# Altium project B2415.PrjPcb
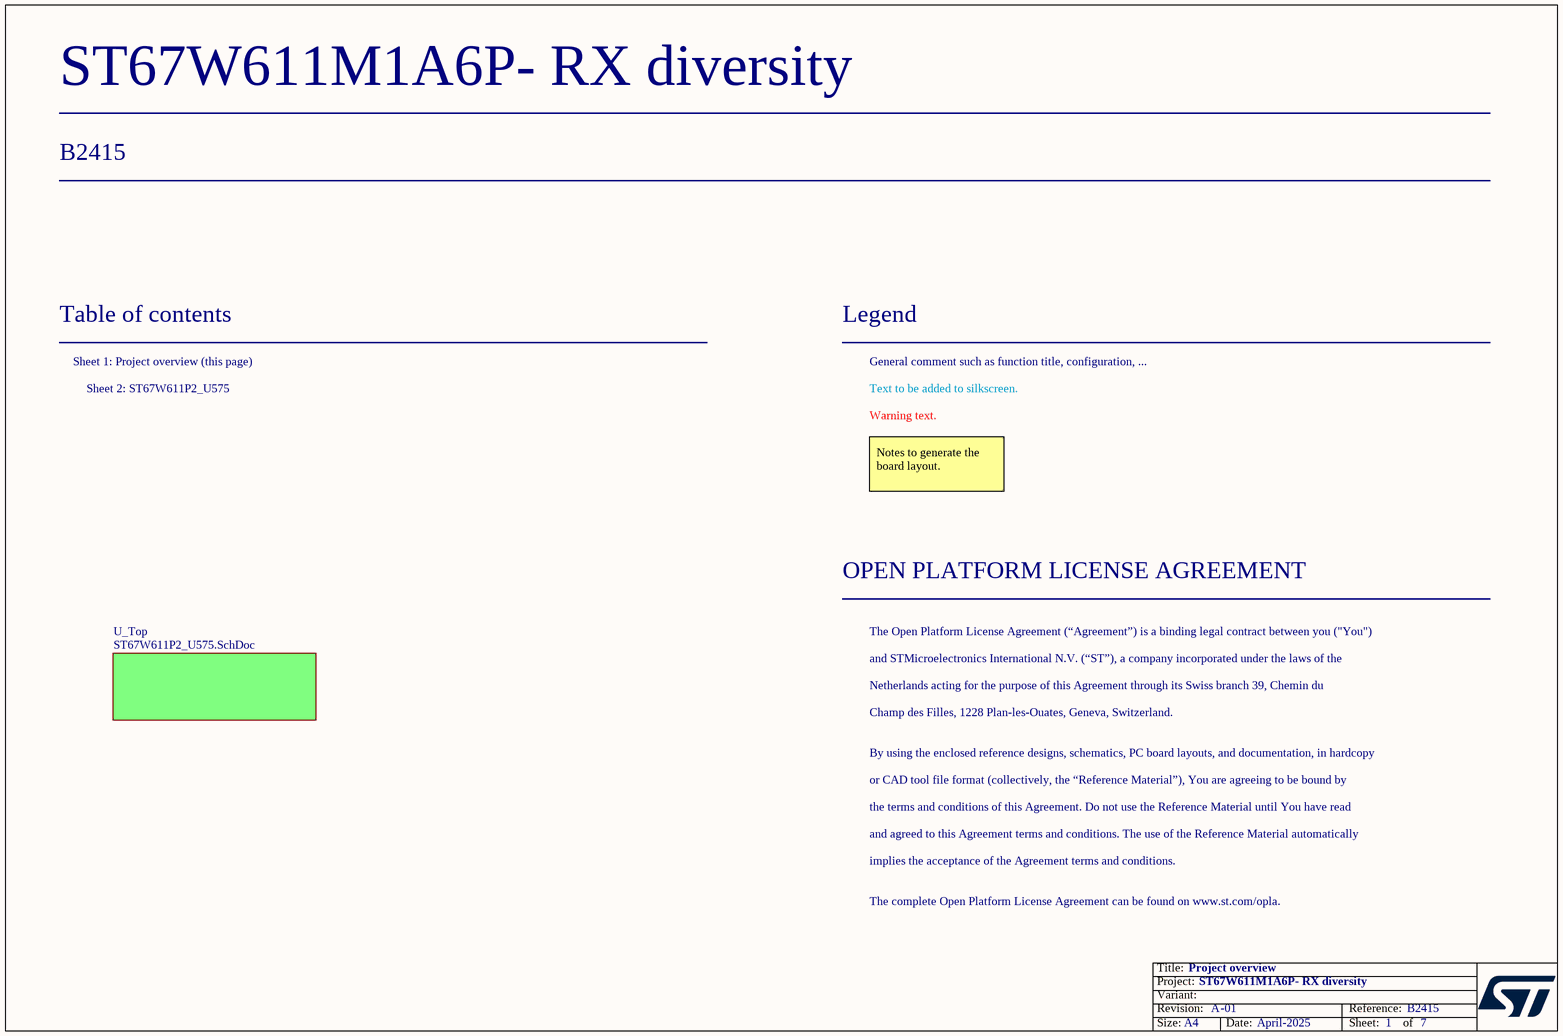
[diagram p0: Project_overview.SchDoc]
Board_Reference: B2415; Board_PCB_Revision: A; Board_Name: ST67W611M1A6P- RX diversity; Board_Document_Date: April-2025; Board_Assembly_Revision: 01
2 sheets, 94 parts. Net scope: global (net labels, ports and power ports of the same name join across sheets).
Board file: B2415.PcbDoc
Sheets:
  Project_overview.SchDoc
    U_Top = ST67W611P2_U575.SchDoc

## Sheet Project_overview.SchDoc: Project overview
size A4; Date: Not used; ApprovedBy: Not used; CheckedBy: Not used; Author: Not used; CompanyName: STMicroelectronics; DrawnBy: Not used; Engineer: Not used; Organization: Not used; Address1: Not used; Address2: Not used; Address3: Not used; Address4: Not used; DocumentNumber: Not used; Revision: Not used; SheetNumber: 1; SheetTotal: 7

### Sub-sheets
U_Top = ST67W611P2_U575.SchDoc: no entries

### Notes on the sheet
- Table of contents
- Sheet 1: Project overview (this page)
- Legend
- General comment such as function title, configuration, ...
- Sheet 2: ST67W611P2_U575
- Text to be added to silkscreen.
- Warning text.
- Notes to generate the board layout.
- OPEN PLATFORM LICENSE AGREEMENT
- The Open Platform License Agreement (“Agreement”) is a binding legal contract between you ("You")
- and STMicroelectronics International N.V. (“ST”), a company incorporated under the laws of the
- Netherlands acting for the purpose of this Agreement through its Swiss branch 39, Chemin du
- Champ des Filles, 1228 Plan-les-Ouates, Geneva, Switzerland.
- By using the enclosed reference designs, schematics, PC board layouts, and documentation, in hardcopy
- or CAD tool file format (collectively, the “Reference Material”), You are agreeing to be bound by
- the terms and conditions of this Agreement. Do not use the Reference Material until You have read
- and agreed to this Agreement terms and conditions. The use of the Reference Material automatically
- implies the acceptance of the Agreement terms and conditions.
- The complete Open Platform License Agreement can be found on www.st.com/opla.

## Sheet ST67W611P2_U575.SchDoc: STM32 microcontroller RF
size A3; Date: Not used; ApprovedBy: Not used; CheckedBy: Not used; Author: Not used; CompanyName: STMicroelectronics; DrawnBy: Not used; Engineer: Not used; Organization: Not used; Address1: Not used; Address2: Not used; Address3: Not used; Address4: Not used; DocumentNumber: Not used; Revision: Not used; SheetNumber: 5; SheetTotal: 7
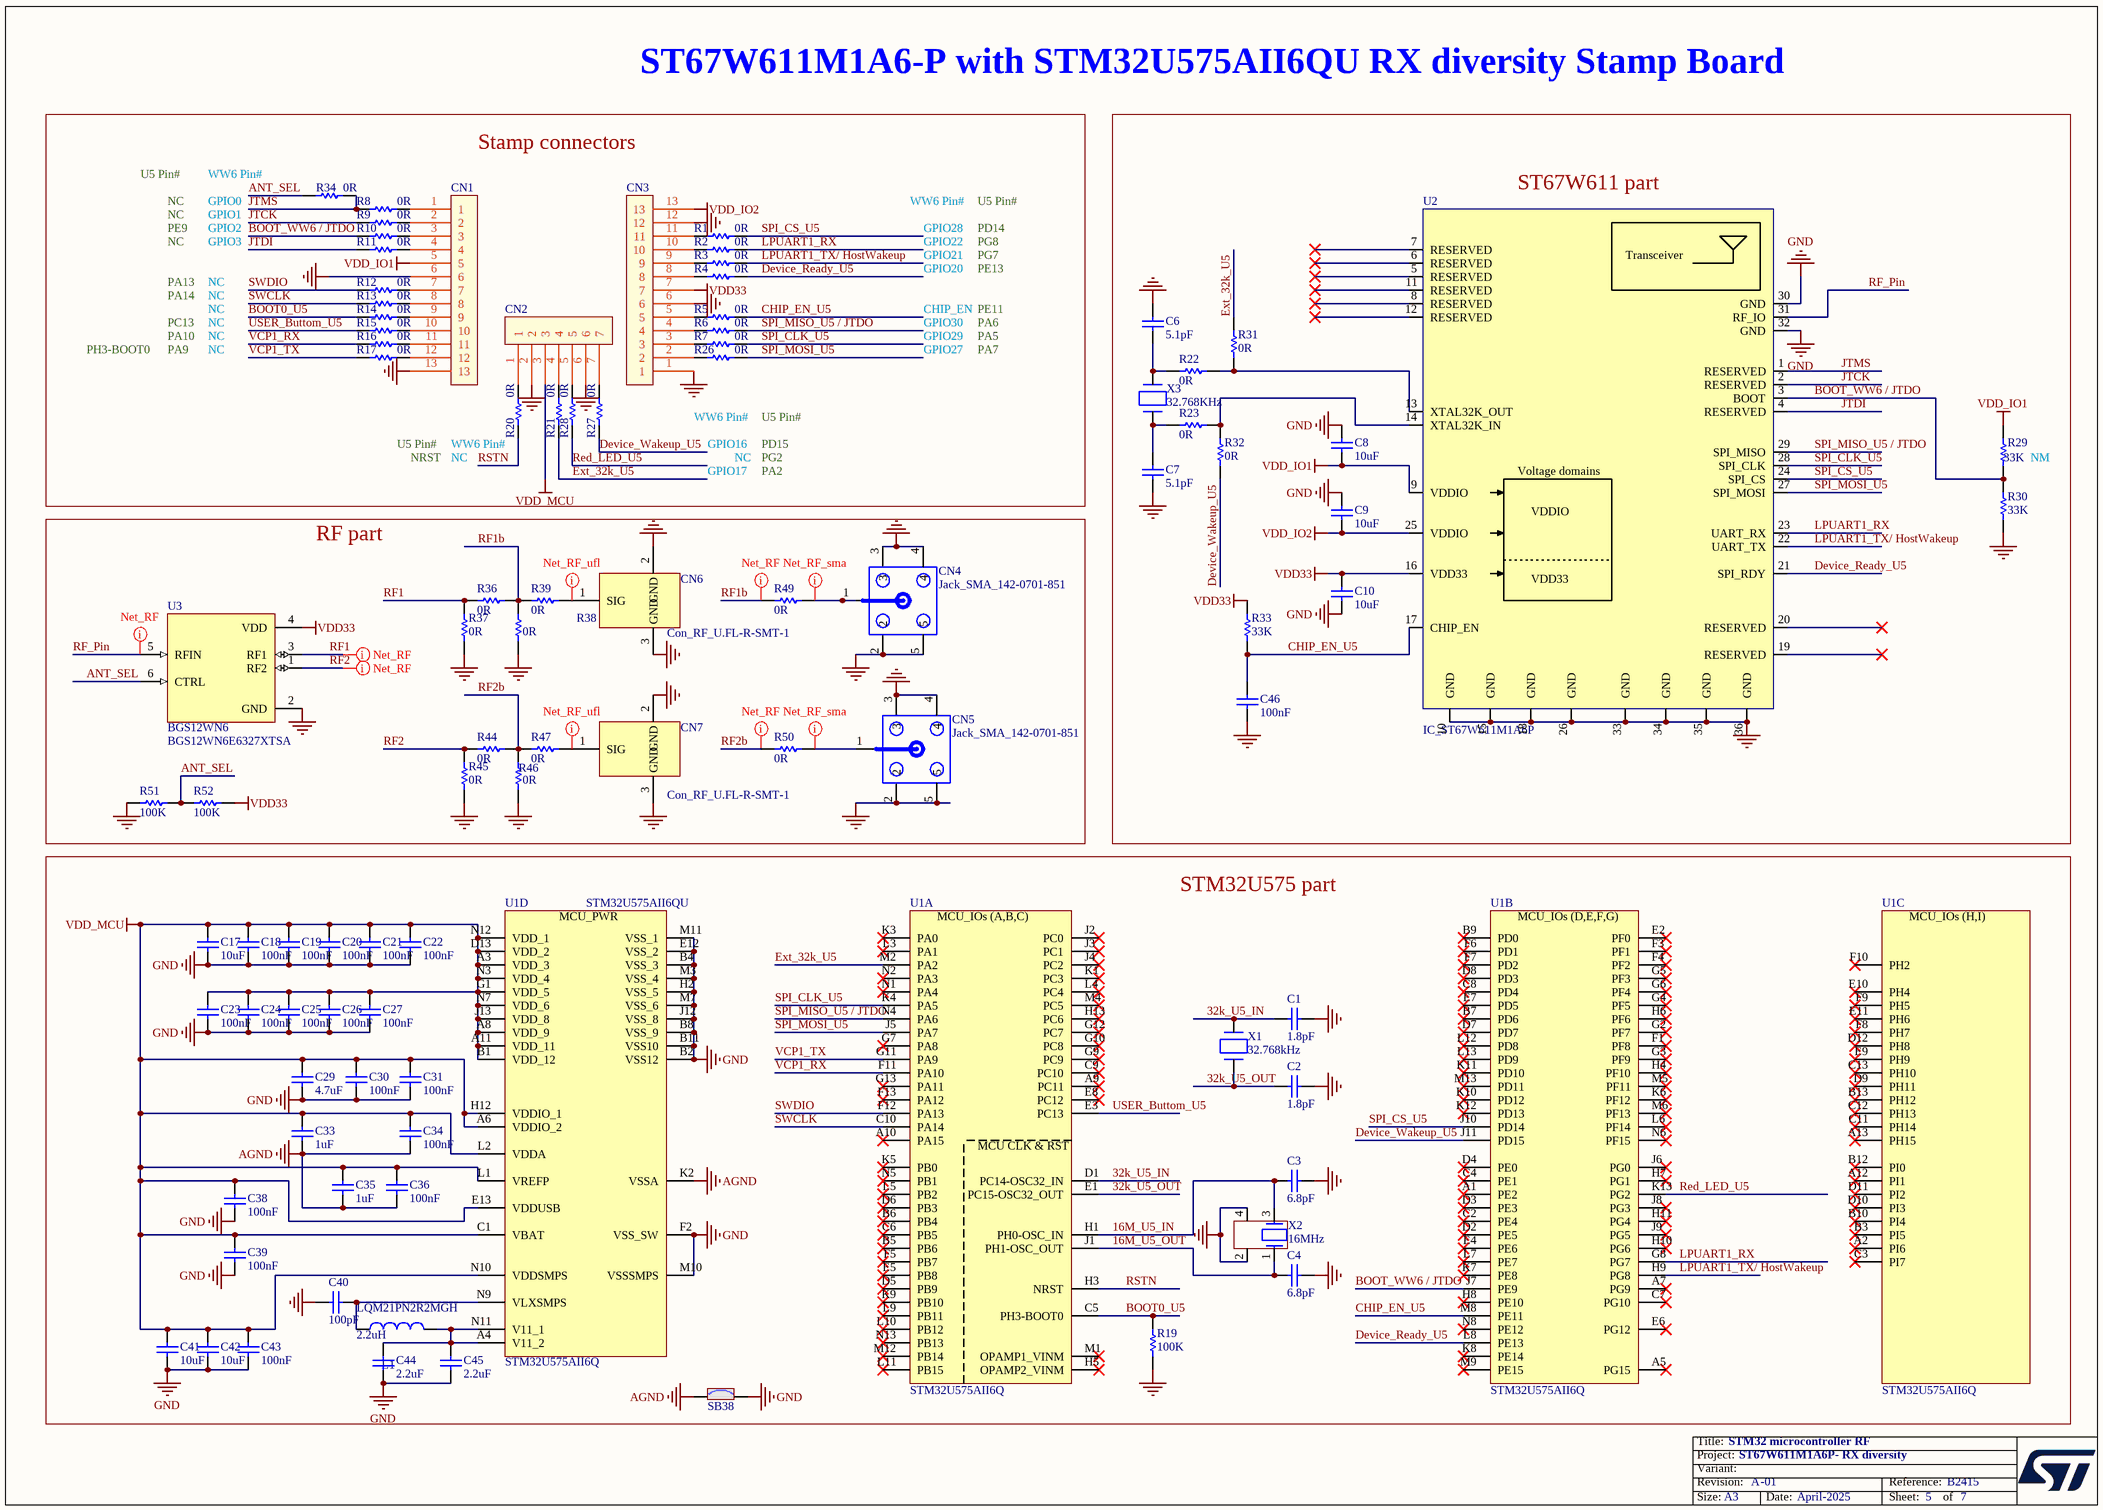
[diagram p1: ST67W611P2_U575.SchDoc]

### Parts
C1  value 1.8pF  [C0402]  (hidden comment: Capacitor)
C2  value 1.8pF  [C0402]  (hidden comment: Capacitor)
C3  value 6.8pF  [C0402]  (hidden comment: Capacitor)
C4  value 6.8pF  [C0402]  (hidden comment: Capacitor)
C6  value 5.1pF  [C0402]  (hidden comment: Capacitor)
C7  value 5.1pF  [C0402]  (hidden comment: Capacitor)
C8  value 10uF  [C0402]  (hidden comment: Capacitor)
C9  value 10uF  [C0402]  (hidden comment: Capacitor)
C10  value 10uF  [C0402]  (hidden comment: Capacitor)
C17  value 10uF  [C0402]  (hidden comment: Capacitor)
C18  value 100nF  [C0402]  (hidden comment: Capacitor)
C19  value 100nF  [C0402]  (hidden comment: Capacitor)
C20  value 100nF  [C0402]  (hidden comment: Capacitor)
C21  value 100nF  [C0402]  (hidden comment: Capacitor)
C22  value 100nF  [C0402]  (hidden comment: Capacitor)
C23  value 100nF  [C0402]  (hidden comment: Capacitor)
C24  value 100nF  [C0402]  (hidden comment: Capacitor)
C25  value 100nF  [C0402]  (hidden comment: Capacitor)
C26  value 100nF  [C0402]  (hidden comment: Capacitor)
C27  value 100nF  [C0402]  (hidden comment: Capacitor)
C29  value 4.7uF  [C0402]  (hidden comment: Capacitor)
C30  value 100nF  [C0402]  (hidden comment: Capacitor)
C31  value 100nF  [C0402]  (hidden comment: Capacitor)
C33  value 1uF  [C0402]  (hidden comment: Capacitor)
C34  value 100nF  [C0402]  (hidden comment: Capacitor)
C35  value 1uF  [C0402]  (hidden comment: Capacitor)
C36  value 100nF  [C0402]  (hidden comment: Capacitor)
C38  value 100nF  [C0402]  (hidden comment: Capacitor)
C39  value 100nF  [C0402]  (hidden comment: Capacitor)
C40  value 100pF  [C0402]  (hidden comment: Capacitor)
C41  value 10uF  [C0402]  (hidden comment: Capacitor)
C42  value 10uF  [C0402]  (hidden comment: Capacitor)
C43  value 100nF  [C0402]  (hidden comment: Capacitor)
C44  value 2.2uF  [C0402]  (hidden comment: Capacitor)
C45  value 2.2uF  [C0402]  (hidden comment: Capacitor)
C46  value 100nF  [C0402]  (hidden comment: Capacitor)
CN1  (no value)  [Stamps_holes_x13]
CN2  (no value)  [Stamps_holes_x7]
CN3  (no value)  [Stamps_holes_x13]
CN4  value Jack_SMA_142-0701-851  [CON_SMA-RF_CINCH_142-0701-851]  (hidden comment: SMA-J-P-H-ST-EM1)
CN5  value Jack_SMA_142-0701-851  [CON_SMA-RF_CINCH_142-0701-851]  (hidden comment: SMA-J-P-H-ST-EM1)
CN6  value Con_RF_U.FL-R-SMT-1  [CON_HRS_U.FL-R-SMT-1]  (hidden comment: U.FL-R-SMT-1)
CN7  value Con_RF_U.FL-R-SMT-1  [CON_HRS_U.FL-R-SMT-1]  (hidden comment: U.FL-R-SMT-1)
L1  value 2.2uH  Manufacturer_Part_Number: LQM21PN2R2MGH  [L0805_H0P9]  (hidden comment: Inductor)
R1  value 0R  [R0201_H0P23]  (hidden comment: Resistor)
R2  value 0R  [R0201_H0P23]  (hidden comment: Resistor)
R3  value 0R  [R0201_H0P23]  (hidden comment: Resistor)
R4  value 0R  [R0201_H0P23]  (hidden comment: Resistor)
R5  value 0R  [R0201_H0P23]  (hidden comment: Resistor)
R6  value 0R  [R0201_H0P23]  (hidden comment: Resistor)
R7  value 0R  [R0201_H0P23]  (hidden comment: Resistor)
R8  value 0R  [R0201_H0P23]  (hidden comment: Resistor)
R9  value 0R  [R0201_H0P23]  (hidden comment: Resistor)
R10  value 0R  [R0201_H0P23]  (hidden comment: Resistor)
R11  value 0R  [R0201_H0P23]  (hidden comment: Resistor)
R12  value 0R  [R0201_H0P23]  (hidden comment: Resistor)
R13  value 0R  [R0201_H0P23]  (hidden comment: Resistor)
R14  value 0R  [R0201_H0P23]  (hidden comment: Resistor)
R15  value 0R  [R0201_H0P23]  (hidden comment: Resistor)
R16  value 0R  [R0201_H0P23]  (hidden comment: Resistor)
R17  value 0R  [R0201_H0P23]  (hidden comment: Resistor)
R19  value 100K  [R0201_H0P23]  (hidden comment: Resistor)
R20  value 0R  [R0201_H0P23]  (hidden comment: Resistor)
R21  value 0R  [R0201_H0P23]  (hidden comment: Resistor)
R22  value 0R  [R0201_H0P23]  (hidden comment: Resistor)
R23  value 0R  [R0201_H0P23]  (hidden comment: Resistor)
R26  value 0R  [R0201_H0P23]  (hidden comment: Resistor)
R27  value 0R  [R0201_H0P23]  (hidden comment: Resistor)
R28  value 0R  [R0201_H0P23]  (hidden comment: Resistor)
R29  value 33K  [R0402]  (hidden comment: Resistor)
R30  value 33K  [R0402]  (hidden comment: Resistor)
R31  value 0R  [R0201_H0P23]  (hidden comment: Resistor)
R32  value 0R  [R0201_H0P23]  (hidden comment: Resistor)
R33  value 33K  [R0402]  (hidden comment: Resistor)
R34  value 0R  [R0201_H0P23]  (hidden comment: Resistor)
R36  value 0R  [R0201_H0P23]  (hidden comment: Resistor)
R37  value 0R  [R0201_H0P23]  (hidden comment: Resistor)
R38  value 0R  [R0201_H0P23]  (hidden comment: Resistor)
R39  value 0R  [R0201_H0P23]  (hidden comment: Resistor)
R44  value 0R  [R0201_H0P23]  (hidden comment: Resistor)
R45  value 0R  [R0201_H0P23]  (hidden comment: Resistor)
R46  value 0R  [R0201_H0P23]  (hidden comment: Resistor)
R47  value 0R  [R0201_H0P23]  (hidden comment: Resistor)
R49  value 0R  [R0201_H0P23]  (hidden comment: Resistor)
R50  value 0R  [R0201_H0P23]  (hidden comment: Resistor)
R51  value 100K  [R0201_H0P23]  (hidden comment: Resistor)
R52  value 100K  [R0201_H0P23]  (hidden comment: Resistor)
SB38  SB_ON  [SOLDER-BRIDGE_R0402-0R]  (value not drawn)
U1  value STM32U575AII6Q  [ICC_UFBGA169_7X7_P050]  (hidden comment: STM32U575AII6QU)  (parts A,B,C,D of 4)
U2  IC_ST67W611M1A6P  [ST67W611M1A6P/B6P]
U3  BGS12WN6  value BGS12WN6E6327XTSA  [ICC_TSNP-6-10_0P7X1P1_P040]
X1  value 32.768kHz  [CRY_NX1610SE_2P]  (hidden comment: XTAL_2_PINS)
X2  value 16MHz  [CRY_NX2016SA_4P]  (hidden comment: XTAL_4_PINS)
X3  value 32.768KHz  [CRY_NX2012SA_2P]  (hidden comment: XTAL_2_PINS)

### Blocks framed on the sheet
Stamp connectors: CN1-CN3 R1-R17 R20 R21 R26-R28 R34
ST67W611 part: C6-C10 C46 R22 R23 R29-R33 U2 X3
RF part: CN4-CN7 R36-R39 R44-R47 R49-R52 U3
STM32U575 part: C1-C4 C17-C27 C29-C31 C33-C36 C38-C45 L1 R19 SB38 U1 X1 X2

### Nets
AGND: C33.1 C34.1 C35.1 C36.1 SB38.1 U1.K2(VSSA)
GND: C1.1 C2.1 C3.1 C4.1 C6.2 C7.1 C8.2 C9.2 C10.1 C17.1 C18.1 C19.1 C20.1 C21.1 C22.1 C23.1 C24.1 C25.1 C26.1 C27.1 C29.1 C30.1 C31.1 C38.1 C39.1 C40.1 C41.1 C42.1 C43.1 C44.1 C45.1 C46.1 CN1.6 CN1.13 CN2.2 CN2.6 CN3.1 CN3.6 CN3.12 CN4.2 CN4.3 CN4.4 CN4.5 CN5.2 CN5.3 CN5.4 CN5.5 CN6.2(GND) CN6.3(GND) CN7.2(GND) CN7.3(GND) R19.2 R30.1 R37.1 R38.1 R45.1 R46.1 R51.1 SB38.2 U1.B2(VSS12) U1.B4(VSS_3) U1.B8(VSS_9) U1.B11(VSS10) U1.E12(VSS_2) U1.F2(VSS_SW) U1.H2(VSS_5) U1.J12(VSS_8) U1.M3(VSS_4) U1.M7(VSS_6) U1.M10(VSSSMPS) U1.M11(VSS_1) U2.10(GND) U2.15(GND) U2.18(GND) U2.26(GND) U2.30(GND) U2.32(GND) U2.33(GND) U2.34(GND) U2.35(GND) U2.36(GND) U3.2(GND) X2.2 X2.4
VDD33: C10.2 CN3.7 R33.2 R52.2 U2.16(VDD33) U3.4(VDD)
VDD_IO1: C8.1 CN1.5 R29.2 U2.9(VDDIO)
VDD_IO2: C9.1 CN3.13 U2.25(VDDIO)
VDD_MCU: C17.2 C18.2 C19.2 C20.2 C21.2 C22.2 C23.2 C24.2 C25.2 C26.2 C27.2 C29.2 C30.2 C31.2 C33.2 C34.2 C35.2 C36.2 C38.2 C39.2 C41.2 C42.2 C43.2 CN2.3 U1.A3(VDD_3) U1.A6(VDDIO_2) U1.A8(VDD_9) U1.A11(VDD_11) U1.B1(VDD_12) U1.C1(VBAT) U1.D13(VDD_2) U1.E13(VDDUSB) U1.G1(VDD_5) U1.H12(VDDIO_1) U1.J13(VDD_8) U1.L1(VREFP) U1.L2(VDDA) U1.N3(VDD_4) U1.N7(VDD_6) U1.N10(VDDSMPS) U1.N12(VDD_1)
16M_U5_IN: C3.2 U1.H1(PH0-OSC_IN) X2.3
16M_U5_OUT: C4.2 U1.J1(PH1-OSC_OUT) X2.1
32k_U5_IN: C1.2 U1.D1(PC14-OSC32_IN) X1.2(X2)
32k_U5_OUT: C2.2 U1.E1(PC15-OSC32_OUT) X1.1(X1)
ANT_SEL: R34.2 R51.2 R52.1 U3.6(CTRL)
BOOT0_U5: R14.2 R19.1 U1.C5(PH3-BOOT0)
BOOT_WW6 / JTDO: R10.2 R29.1 R30.2 U1.J7(PE9) U2.3(BOOT)
CHIP_EN_U5: C46.2 R5.1 R33.1 U1.M8(PE11) U2.17(CHIP_EN)
Device_Ready_U5: R4.1 U1.L8(PE13) U2.21(SPI_RDY)
Device_Wakeup_U5: R27.2 R32.2 U1.J11(PD15)
Ext_32k_U5: R21.2 R31.1 U1.M2(PA2)
JTCK: R9.2 U2.2(RESERVED)
JTDI: R11.2 U2.4(RESERVED)
JTMS: R8.2 R34.1 U2.1(RESERVED)
LPUART1_RX: R2.1 U1.G8(PG7) U2.23(UART_RX)
LPUART1_TX/ HostWakeup: R3.1 U1.H9(PG8) U2.22(UART_TX)
Red_LED_U5: R28.2 U1.K13(PG2)
RF1: R36.1 R37.2 U3.3(RF1)
RF1b: R36.2 R38.2 R39.2 R49.1
RF2: R44.1 R45.2 U3.1(RF2)
RF2b: R44.2 R46.2 R47.2 R50.1
RF_Pin: U2.31(RF_IO) U3.5(RFIN)
RSTN: R20.2 U1.H3(NRST)
SPI_CLK_U5: R7.1 U1.K4(PA5) U2.28(SPI_CLK)
SPI_CS_U5: R1.1 U1.J10(PD14) U2.24(SPI_CS)
SPI_MISO_U5 / JTDO: R6.1 U1.N4(PA6) U2.29(SPI_MISO)
SPI_MOSI_U5: R26.1 U1.J5(PA7) U2.27(SPI_MOSI)
SWCLK: R13.2 U1.C10(PA14)
SWDIO: R12.2 U1.F12(PA13)
USER_Buttom_U5: R15.2 U1.E3(PC13)
VCP1_RX: R16.2 U1.F11(PA10)
VCP1_TX: R17.2 U1.G11(PA9)
NetC6_1: C6.1 R22.2 X3.2(X2)
NetC7_2: C7.2 R23.2 X3.1(X1)
NetC40_2: C40.2 L1.1 U1.N9(VLXSMPS)
NetC44_2: C44.2 C45.2 L1.2 U1.A4(V11_2) U1.N11(V11_1)
NetCN1_1: CN1.1 R8.1
NetCN1_2: CN1.2 R9.1
NetCN1_3: CN1.3 R10.1
NetCN1_4: CN1.4 R11.1
NetCN1_7: CN1.7 R12.1
NetCN1_8: CN1.8 R13.1
NetCN1_9: CN1.9 R14.1
NetCN1_10: CN1.10 R15.1
NetCN1_11: CN1.11 R16.1
NetCN1_12: CN1.12 R17.1
NetCN2_1: CN2.1 R20.1
NetCN2_4: CN2.4 R21.1
NetCN2_5: CN2.5 R28.1
NetCN2_7: CN2.7 R27.1
NetCN3_2: CN3.2 R26.2
NetCN3_3: CN3.3 R7.2
NetCN3_4: CN3.4 R6.2
NetCN3_5: CN3.5 R5.2
NetCN3_8: CN3.8 R4.2
NetCN3_9: CN3.9 R3.2
NetCN3_10: CN3.10 R2.2
NetCN3_11: CN3.11 R1.2
NetCN4_1: CN4.1 R49.2
NetCN5_1: CN5.1 R50.2
NetCN6_1: CN6.1(SIG) R39.1
NetCN7_1: CN7.1(SIG) R47.1
NetR22_1: R22.1 R31.2 U2.13(XTAL32K_OUT)
NetR23_1: R23.1 R32.1 U2.14(XTAL32K_IN)

Not connected (* = marked no-connect by the designer): U1 A1(PE2)* A2(PI6)* A5(PG15)* A7(PG9)* A9(PC11)* A10(PA15)* A12(PI1)* A13(PH15)* B3(PI5)* B5(PB6)* B6(PB4)* B7(PD6)* B9(PD0)* B10(PI4)* B12(PI0)* B13(PH12)* C2(PE4)* C3(PI7)* C4(PE1)* C6(PB5)* C7(PG10)* C8(PD4)* C9(PC10)* C11(PH14)* C12(PH13)* C13(PH10)* D2(PE5)* D3(PE3)* D4(PE0)* D5(PB9)* D6(PB3)* D7(PD7)* D8(PD3)* D9(PH11)* D10(PI3)* D11(PI2)* D12(PH8)* E2(PF0)* E4(PE6)* E5(PB8)* E6(PG12)* E7(PD5)* E8(PC12)* E9(PH9)* E10(PH4)* E11(PH6)* F1(PF8)* F3(PF1)* F4(PF2)* F5(PB7)* F6(PD1)* F7(PD2)* F8(PH7)* F9(PH5)* F10(PH2)* F13(PA12)* G2(PF7)* G3(PF9)* G4(PF5)* G5(PF3)* G6(PF4)* G7(PA8)* G9(PC9)* G10(PC8)* G12(PC7)* G13(PA11)* H4(PF10)* H5(OPAMP2_VINM)* H6(PF6)* H7(PG1)* H8(PE10)* H10(PG6)* H11(PG4)* H13(PC6)* J2(PC0)* J3(PC1)* J4(PC2)* J6(PG0)* J8(PG3)* J9(PG5)* K1(PC3)* K3(PA0)* K5(PB0)* K6(PF12)* K7(PE8)* K8(PE14)* K9(PB10)* K10(PD12)* K11(PD10)* K12(PD13)* L3(PA1)* L4(PC4)* L5(PB2)* L6(PF14)* L7(PE7)* L9(PB11)* L10(PB12)* L11(PB15)* L12(PD8)* L13(PD9)* M1(OPAMP1_VINM)* M4(PC5)* M5(PF11)* M6(PF13)* M9(PE15)* M12(PB14)* M13(PD11)* N1(PA4)* N2(PA3)* N5(PB1)* N6(PF15)* N8(PE12)* N13(PB13)*; U2 5(RESERVED)* 6(RESERVED)* 7(RESERVED)* 8(RESERVED)* 11(RESERVED)* 12(RESERVED)* 19(RESERVED)* 20(RESERVED)*

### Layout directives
rule Clearance Constraint [Clearance = 6.7mil]: NetCN4_1, NetCN5_1, NetCN6_1, NetCN7_1, RF1, RF1b, RF2, RF2b, RF_Pin

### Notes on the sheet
- ST67W611M1A6-P with STM32U575AII6QU RX diversity Stamp Board
- U5 Pin#
- WW6 Pin#
- NC
- PE9
- GPIO0
- GPIO1
- GPIO2
- GPIO3
- GPIO28
- GPIO22
- PD14
- PG8
- PA13
- PA14
- GPIO21
- GPIO20
- CHIP_EN
- PG7
- PE13
- PE11
- PH3-BOOT0
- PC13
- PA10
- PA9
- GPIO30
- GPIO29
- GPIO27
- PA6
- PA5
- PA7
- (near R20) WW6 Pin#
- GPIO16
- PD15
- NRST
- GPIO17
- PG2
- PA2
- NM

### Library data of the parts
C1 C2 = MCD-02995: Capacitor, MLCC, 1.8pF, 50V, C0G, +/-0.25pF, 0402, T=0.5mm; Part_Preference: Recommended; Manufacturer: MURATA; Manufacturer_Part_Number: GRM1555C1H1R8CA01; Order_Code_RS: 723-5357; Component_Country_Of_Origin: Japan°; ShowFields: YES; ID: 5111
C3 C4 = MCD-00674: Capacitor, MLCC, 6.8pF, 50V, NPO, +/-0.25pF, 0402, T=0.5mm; Part_Preference: Recommended; Manufacturer: YAGEO; Manufacturer_Part_Number: CC0402CRNPO9BN6R8; Component_Country_Of_Origin: China; ShowFields: YES; ID: 3068
C6 C7 = MCD-00003: Capacitor, MLCC, 5.1pF, 50V, NPO, +/-0.25pF, 0402, T=0.5mm; Manufacturer_Part_Number: CC0402CRNPO9BN5R1; Manufacturer: YAGEO; Part_Preference: Recommended; Component_Country_Of_Origin: China; ShowFields: YES; ID: 2477
C8-C10 C17 C41 C42 = MCD-01532: Capacitor, MLCC, 10uF, 10V, X5R, +/-20%, 0402, T=0.5mm; Part_Preference: Recommended; Manufacturer: MURATA; Manufacturer_Part_Number: GRM155R61A106ME11; Component_Country_Of_Origin: Japan°°; ShowFields: YES; ID: 3632
C18-C27 C30 C31 C34 C36 C38 C39 C43 = MCD-00102: Capacitor, MLCC, 100nF, 16V, X7R, +/-10%, 0402, T=0.5mm; Part_Preference: Not recommended; Manufacturer: YAGEO; Manufacturer_Part_Number: CC0402KRX7R7BB104; Order_Code_RS: 616-9701; Component_Country_Of_Origin: China; ShowFields: YES; ID: 2771
C29 = MCD-03816: Capacitor, MLCC, 4.7uF, 6V3, X6S, +/-22%, 0402, T=0.5mm; Part_Preference: Recommended; Manufacturer: MURATA; Manufacturer_Part_Number: GRM155C80J475ME01; Component_Country_Of_Origin: China, Japan, Philippines, Singapore; ShowFields: YES; ID: 5932
C33 C35 = MCD-00095: Capacitor, MLCC, 1uF, 25V, X5R, +/-10%, 0402, T=0.5mm; Part_Preference: Recommended; Manufacturer: MURATA; Manufacturer_Part_Number: GRM155R61E105KA12; Partial_Alternate_Internal_Part_Number: MCD-04188; Order_Code_RS: 2218855; Component_Country_Of_Origin: Japan°°; ShowFields: YES; ID: 2772
C40 = MCD-00205: Capacitor, MLCC, 100pF, 50V, NPO, +/-5%, 0402, T=0.5mm; Part_Preference: Recommended; Manufacturer: YAGEO; Manufacturer_Part_Number: CC0402JRNPO9BN101; Component_Country_Of_Origin: China; ShowFields: YES; ID: 2658
C44 C45 = MCD-01823: Capacitor, MLCC, 2.2uF, 6V3, X5R,+/-10%, 0402, T=0.5mm; Part_Preference: Recommended; Manufacturer: MURATA; Manufacturer_Part_Number: GRM155R60J225KE95D; Partial_Alternate_Internal_Part_Number: MCD-03566; Order_Code_RS: 172-6478; Component_Country_Of_Origin: Japan°°; Alternate_EMS: A; ShowFields: YES; ID: 3923
C46 = MCD-00006: Capacitor, MLCC, 100nF, 16V, X7R, +/-10%, 0402, T=0.5mm; Part_Preference: Recommended; Manufacturer: YAGEO; Manufacturer_Part_Number: CC0402KRX7R7BB104; Partial_Alternate_Internal_Part_Number: MCD-03299; Order_Code_RS: 9402047; Component_Country_Of_Origin: China; ShowFields: YES; ID: 2474
CN1 CN3 = hole_2_54_x13
CN2 = hole_2_54_x7
CN4 CN5 = MCD-02072: Jack_SMA, VR, PCB edge, 50R, T=7.92mm; Part_Type: Connector; Part_Preference: Forbidden; Manufacturer: CINCH; Manufacturer_Part_Number: 142-0701-851; Order_Code_RS: 885-7532; Component_Country_Of_Origin: USA°°; ShowFields: YES; ID: 4172
CN6 CN7 = MCD-01583: Connector_RF, 0Hz to 6GHz, 50R, VR, SMD, T= 1.25mm; BMS_Part_Number: 9187005; Part_Preference: Recommended; Manufacturer: HIROSE; Order_Code_RS: 557-981; Component_Country_Of_Origin: Japan, Malaysia; ShowFields: YES; ID: 3683
L1 = MCD-01060: Inductor, 2.2uH, +/-20%, 0.7A, 0R156, 0805, T=0.9mm; Manufacturer: MURATA; Part_Preference: Recommended; Order_Code_RS: 166-9883; Component_Country_Of_Origin: Japan°°; ShowFields: YES; ID: 2963
R1-R17 R20-R23 R26-R28 R31 R32 R34 R36-R39 R44-R47 R49 R50 = MCD-02450: Resistor, 0R, 0201, 1/20W; Part_Preference: Recommended; Manufacturer: YAGEO; Manufacturer_Part_Number: RC0201JR-070RP; Component_Country_Of_Origin: China; ShowFields: YES; ID: 4556
R19 R51 R52 = MCD-03041: Resistor, 100K, 0201, +/-1%, 1/20W; Part_Preference: Recommended; Manufacturer: YAGEO; Manufacturer_Part_Number: RC0201FR-07100KL; Order_Code_RS: 198-7555; Component_Country_Of_Origin: China; ShowFields: YES; ID: 5157
R29 R30 R33 = MCD-00258: Resistor, 33K, 0402, +/-1%, 1/16W; Part_Preference: Recommended; Manufacturer: YAGEO; Manufacturer_Part_Number: RC0402FR-0733KL; Component_Country_Of_Origin: China; ShowFields: YES; ID: 2611
SB38 = MCD-01618: Resistor, 0R, SB0402, 5%, 0.063W; Manufacturer_Part_Number: RC0402JR-070RL; Manufacturer: YAGEO; Part_Preference: Recommended; ShowFields: YES; ID: 3718; Order_Code_RS: 618-5804; Component_Country_Of_Origin: China
U1 = MCD-01928: MCU, ARM Cortex-M33 32-bit, 2MB Flash, 786KB RAM, With Crypto, SMPS; Part_Type: IC; Part_Preference: Recommended; Manufacturer: STMICROELECTRONICS; Manufacturer_HQ_COO: EU; Component_Country_Of_Origin: Taiwan; ShowFields: YES; ID: 4028
U3 = MCD-03680: IC, Wideband SPDT Diversity Switch with High Switching Speed; Part_Preference: Recommended; Manufacturer: INFINEON; Order_Code_RS: 258-0675; Component_Country_Of_Origin: Malaysia°; ShowFields: YES; ID: 5796
X1 = MCD-02291: Crystal, 32.768kHz, 9pF, +/-20ppm, 70KR, 1.6x1.0mm; Part_Type: Crystal_Osc; Part_Preference: Recommended; Manufacturer: NDK; Manufacturer_Part_Number: NX1610SE-32.768KHz-EXS00A-MU01499; Component_Country_Of_Origin: Japan; ShowFields: YES; ID: 4391
X2 = MCD-01476: Crystal, 16 MHz, 8pF, +/-20ppm, 200R, 2.0x1.6mm; BMS_Part_Number: 9157046; Part_Type: Crystal_Osc; Part_Preference: Recommended; Manufacturer: NDK; Manufacturer_Part_Number: NX2016SA-16MHz-EXS00A-CS07826; Component_Country_Of_Origin: Japan; ShowFields: YES; ID: 3576
X3 = MCD-01479: Crystal, 32.768kHz, 6pF, +/-20ppm, 80K, 2.05x1.2mm; Part_Type: Crystal_Osc; Manufacturer_Part_Number: NX2012SA-32.768KHz-EXS00A-MU00527; Manufacturer: NDK; BMS_Part_Number: 9157049; Part_Preference: Recommended; Component_Country_Of_Origin: Japan; ShowFields: YES; ID: 3579

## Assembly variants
Singleband: all parts fitted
